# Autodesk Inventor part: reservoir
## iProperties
Shininess: 21.0
Length Units: 11269
Angle Units: 11279
Time Units: 11290
Mass Units: 11283
Length Display Precision: 3
Angle Display Precision: 2
Compacted: True
Created: 2001-12
Part Number: reservoir
Material: Par défaut
Document SubType Name: Modélisation
Designer: pichon
Density: 0.0
Volumn: 0.0
Area: 0.0
PropertySet Name: Model Information
Control State: 0
Master: False
Checked Out: False
Author: pichon
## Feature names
1. Révolution1 [Revolution]
2. Extrusion1
3. Extrusion2
